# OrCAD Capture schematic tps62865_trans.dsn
size D; title: TPS62865 2.4-V to 5.5-V Input, 4-A Synchronous Step-Down; rev: 1.1; note: Datasheet: SLUSDN8           EVM: SLUUCE0
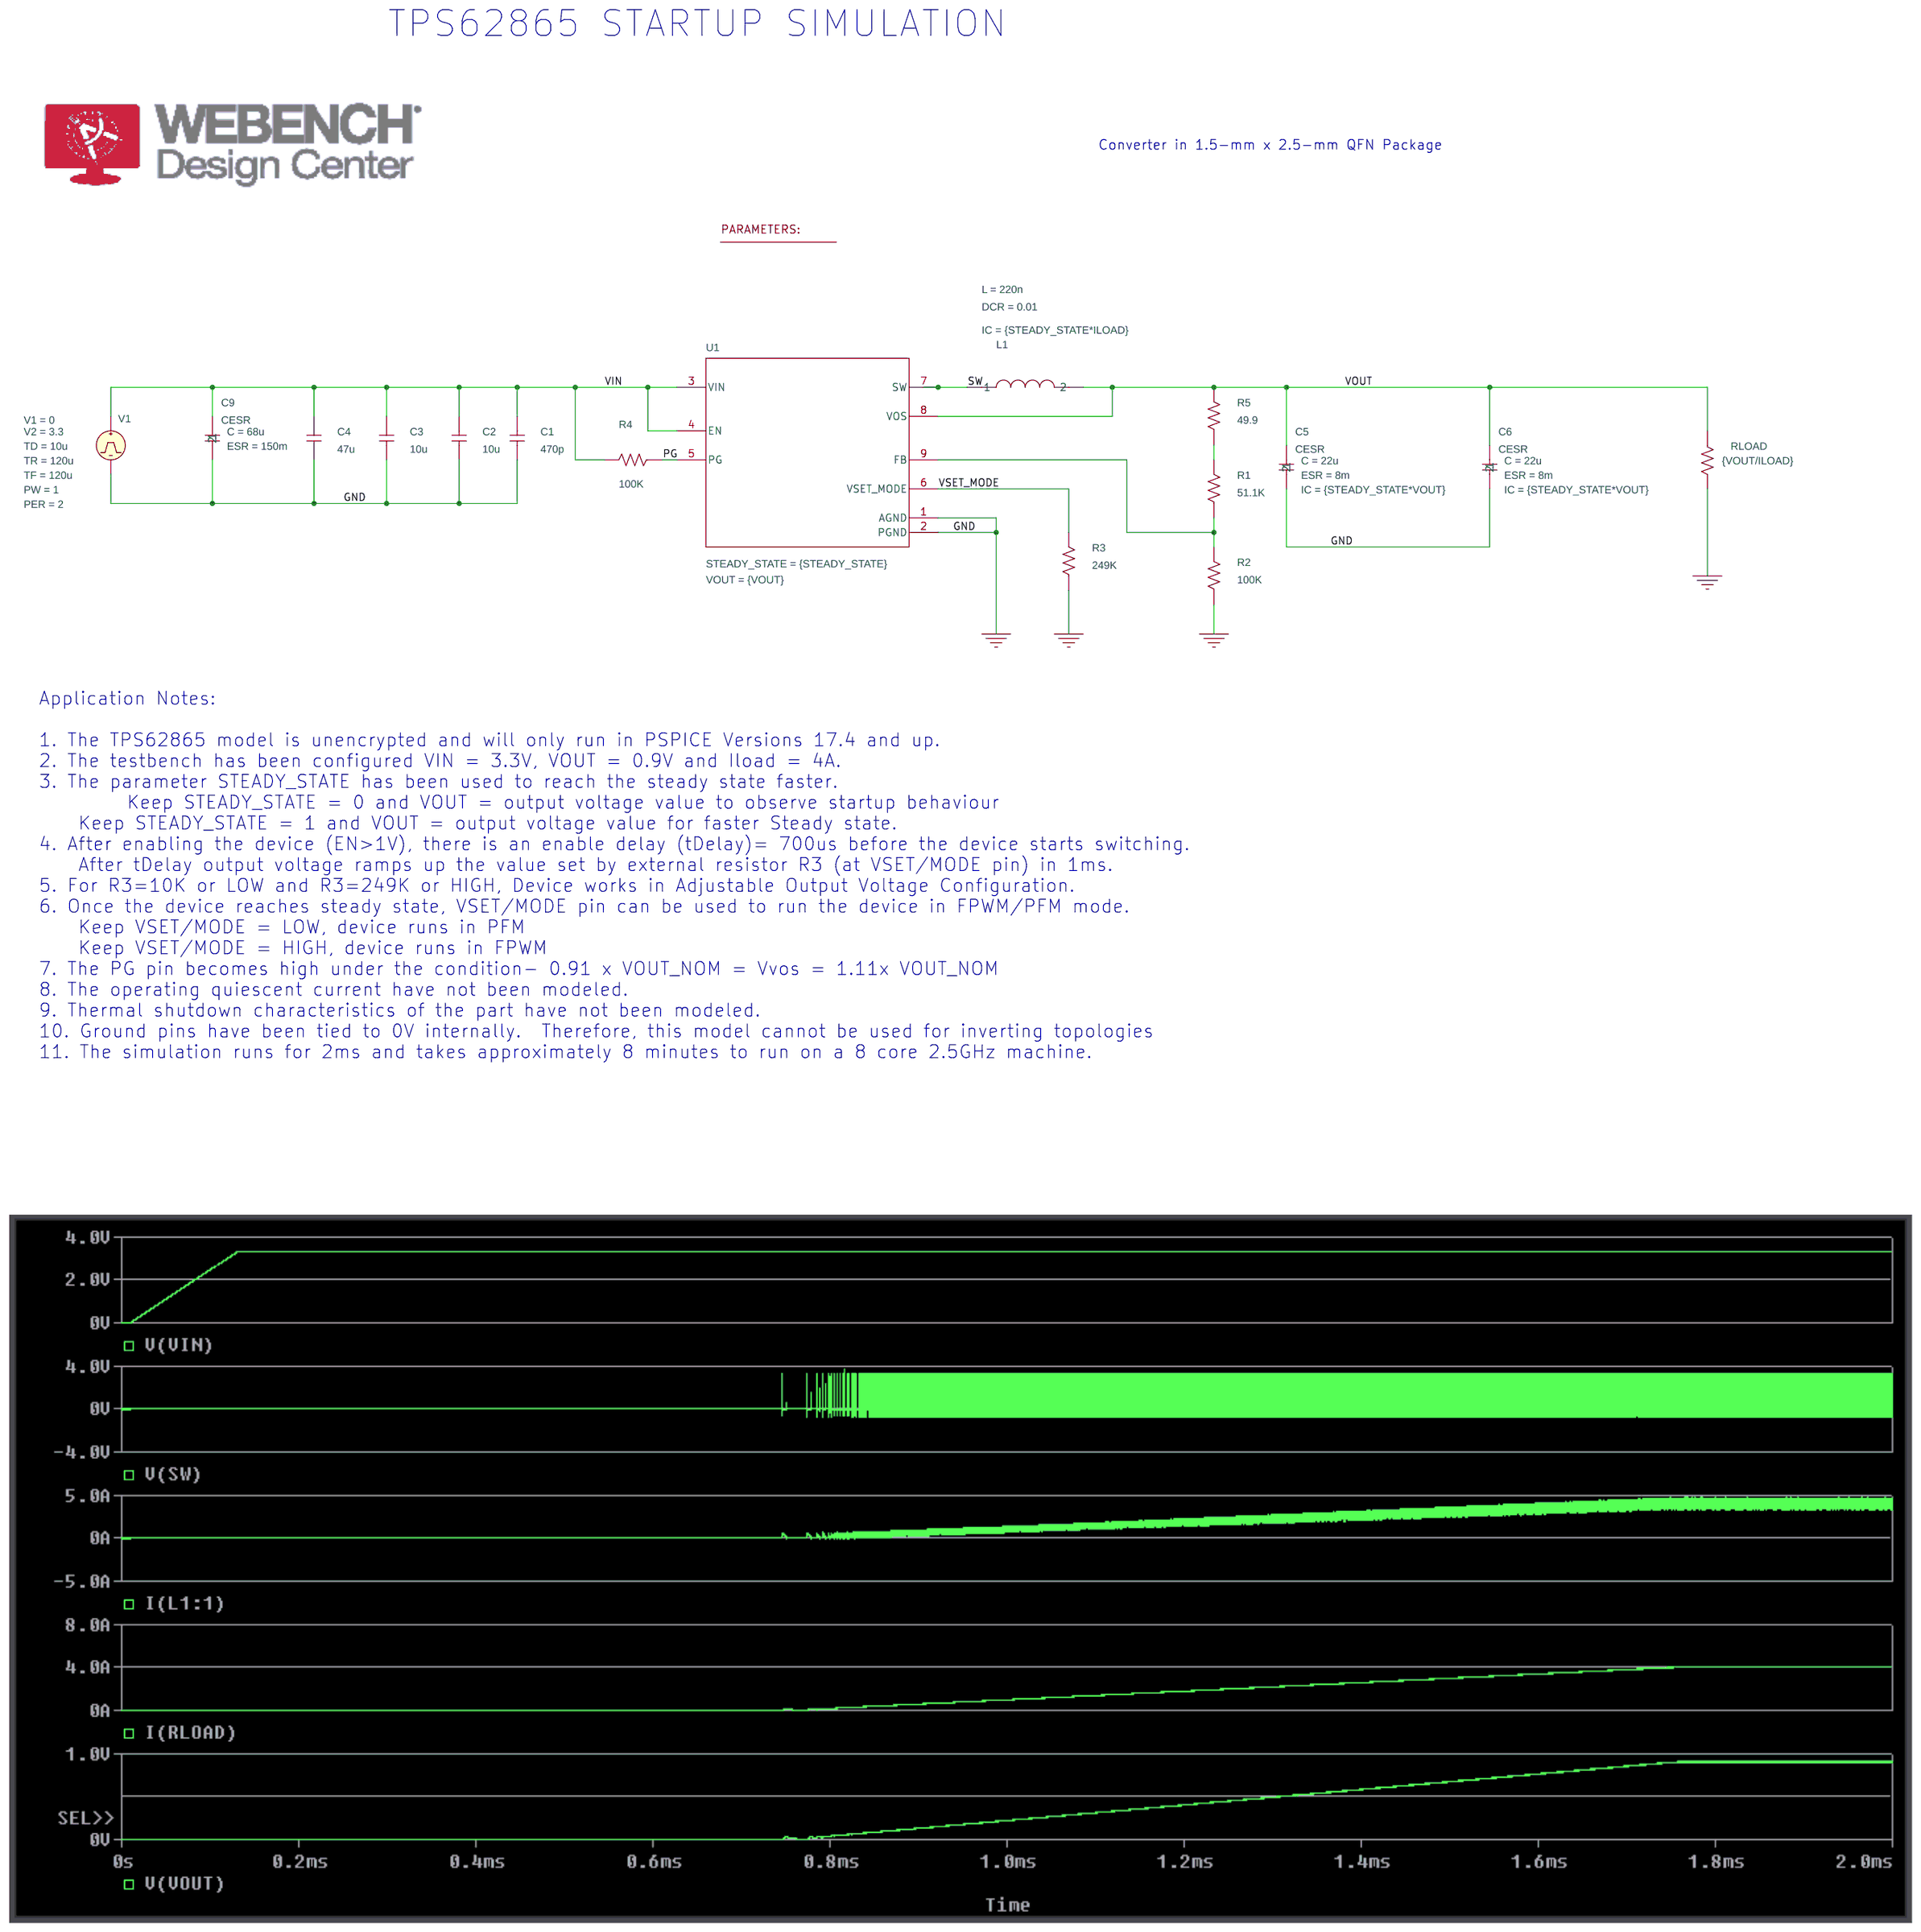
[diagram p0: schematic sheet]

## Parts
5  PARAM
C1  470p  [RAD/CK05]
C2  10u  [RAD/CK05]
C3  10u  [RAD/CK05]
C4  47u  [RAD/CK05]
C5  CESR
C6  CESR
C9  CESR
L1  LDCR
R1  51.1K  [AX/RC05]
R2  100K  [AX/RC05]
R3  249K  [AX/RC05]
R4  100K  [AX/RC05]
R5  49.9  [AX/RC05]
RLOAD  {VOUT/ILOAD}  [AX/RC05]
U1  Value  [RQY0009A-MFG]
V1  VPULSE

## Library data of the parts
5 = PARAM: ILOAD: 4; STEADY_STATE: 0; VOUT: 0.9
C1-C4 = C
C5 = CESR: C: 22u; ESL: 0; ESR: 8m; IC: {STEADY_STATE*VOUT}; PSpiceTemplate: X^@REFDES %1 %2 @MODEL PARAMS: ?C|C=@C||C=10U| ?ESR|ESR=@ESR||ESR=2M| ?ESL|ESL=@ESL||ESL=1N| ?IC|IC=@IC||IC=0|
C6 = CESR_2: C: 22u; ESL: 0; ESR: 8m; IC: {STEADY_STATE*VOUT}; PSpiceTemplate: X^@REFDES %1 %2 @MODEL PARAMS: ?C|C=@C||C=10U| ?ESR|ESR=@ESR||ESR=2M| ?ESL|ESL=@ESL||ESL=1N| ?IC|IC=@IC||IC=0|
C9 = CESR_1: C: 68u; ESR: 150m; PSpiceTemplate: X^@REFDES %1 %2 @MODEL PARAMS: ?C|C=@C||C=10U| ?ESR|ESR=@ESR||ESR=2M| ?ESL|ESL=@ESL||ESL=1N| ?IC|IC=@IC||IC=0|
L1 = LDCR: DCR: 0.01; IC: {STEADY_STATE*ILOAD}; L: 220n
R1-R5 RLOAD = R
U1 = TPS62865RQY_TRANS: STEADY_STATE: {STEADY_STATE}; VOUT: {VOUT}
V1 = VPULSE: PER: 2; PW: 1; TD: 10u; TF: 120u; TR: 120u; V1: 0; V2: 3.3

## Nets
VIN: C1.2 C2.2 C3.2 C4.2 C9.1 R4.2 U1.3(VIN) U1.4(EN) V1.1(+)
0: C1.1 C2.1 C3.1 C4.1 C5.2 C6.2 C9.2 R2.1 R3.1 RLOAD.2 U1.1(AGND) U1.2(PGND) V1.2(-)
PG: R4.1 U1.5(PG)
SW: L1.1 U1.7(SW)
VOUT: C5.1 C6.1 L1.2 R5.2 RLOAD.1 U1.8(VOS)
VSET_MODE: R3.2 U1.6(VSET_MODE)
N16508776: R1.2 R5.1
N16508814: R1.1 R2.2 U1.9(FB)

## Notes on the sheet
- TPS62865 STARTUP SIMULATION
- Converter in 1.5-mm x 2.5-mm QFN Package
- Application Notes:
  1. The TPS62865 model is unencrypted and will only run in PSPICE Versions 17.4 and up.
  2. The testbench has been configured VIN = 3.3V, VOUT = 0.9V and Iload = 4A.
  3. The parameter STEADY_STATE has been used to reach the steady state faster.
  	    Keep STEADY_STATE = 0 and VOUT = output voltage value to observe startup behaviour
      Keep STEADY_STATE = 1 and VOUT = output voltage value for faster Steady state.
  4. After enabling the device (EN>1V), there is an enable delay (tDelay)= 700us before the device starts switching.
      After tDelay output voltage ramps up the value set by external resistor R3 (at VSET/MODE pin) in 1ms.
  5. For R3=10K or LOW and R3=249K or HIGH, Device works in Adjustable Output Voltage Configuration.
  6. Once the device reaches steady state, VSET/MODE pin can be used to run the device in FPWM/PFM mode.
      Keep VSET/MODE = LOW, device runs in PFM
      Keep VSET/MODE = HIGH, device runs in FPWM
  7. The PG pin becomes high under the condition- 0.91 x VOUT_NOM = Vvos = 1.11x VOUT_NOM
  8. The operating quiescent current have not been modeled.
  9. Thermal shutdown characteristics of the part have not been modeled.
  10. Ground pins have been tied to 0V internally.  Therefore, this model cannot be used for inverting topologies
  11. The simulation runs for 2ms and takes approximately 8 minutes to run on a 8 core 2.5GHz machine.
